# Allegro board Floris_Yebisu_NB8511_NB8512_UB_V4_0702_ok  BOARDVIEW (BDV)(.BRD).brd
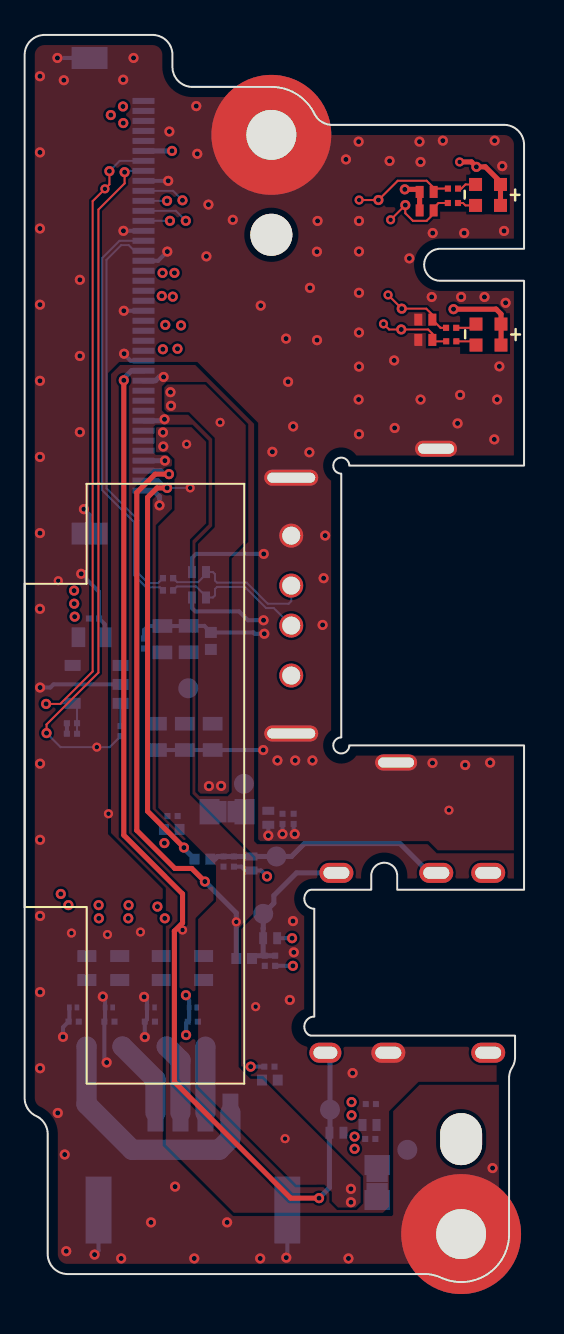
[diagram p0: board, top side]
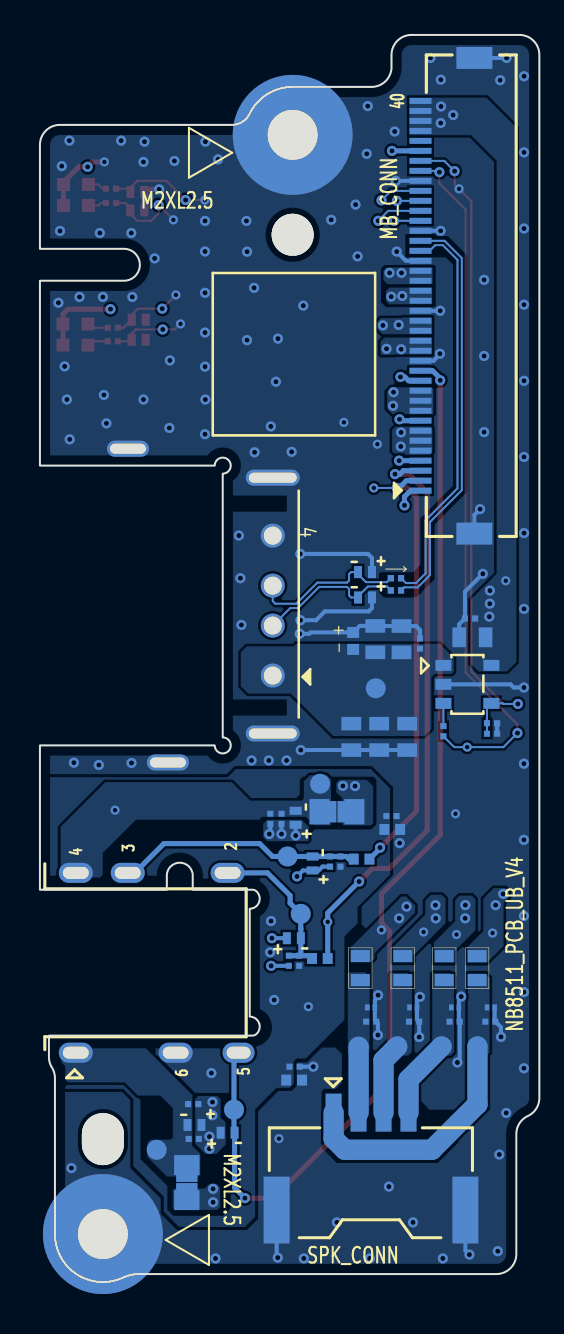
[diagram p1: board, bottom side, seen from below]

Outline 25 x 62.18 mm; copper layers: TOP, GND02, L3, L4, GND05, BOTTOM. Coordinates in mm from the lower left corner of the outline.

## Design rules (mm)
net group DP1: nets USB2_P4_TYPEA_DN_CONN USB2_P4_TYPEA_DP_CONN
net group USB2_P4_D: nets USB2_P4_DN USB2_P4_DP
nets with their own width: min track width 0.203; nets +V3P3A +V5P0A

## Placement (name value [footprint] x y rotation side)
5VUSB1  C40_1  [CMP_40]  8.19 29.49 90 bottom
CA35  C0201X5R104K6R3NTA+C0201X5R104K6R3NJA~~GRM033R60J104KE19D~~CC0201KRX5R5BB104  [C0201]  12.25 10.56 0 bottom
CA38  C0201C0G101J250NTA+C0201C0G101J250NJA~~GRM0335C1E101JD01D~~CC0201JRNPO8BN101  [C0201]  17.33 8.68 180 bottom
CA39  C0201C0G101J250NTA+C0201C0G101J250NJA~~GRM0335C1E101JD01D~~CC0201JRNPO8BN101  [C0201]  13.47 22.96 270 bottom
CA40  C0201C0G101J250NTA+C0201C0G101J250NJA~~GRM0335C1E101JD01D~~CC0201JRNPO8BN101  [C0201]  12.54 15.86 270 bottom
CA41  C0201C0G101J250NTA+C0201C0G101J250NJA~~GRM0335C1E101JD01D~~CC0201JRNPO8BN101  [C0201]  10.48 20.82 270 bottom
CA42  C0201X7R102K250NTA+C0201X7R102K250NJA~~GRM033R71E102KA01D~~CC0201KRX7R8BB102  [C0201]  2.45 12.81 0 bottom
CA43  C0201X7R102K250NTA+C0201X7R102K250NJA~~GRM033R71E102KA01D~~CC0201KRX7R8BB102  [C0201]  8.42 12.81 0 bottom
CA44  C0201X7R102K250NTA+C0201X7R102K250NJA~~GRM033R71E102KA01D~~CC0201KRX7R8BB102  [C0201]  4.24 12.81 0 bottom
CA45  C0201X7R102K250NTA+C0201X7R102K250NJA~~GRM033R71E102KA01D~~CC0201KRX7R8BB102  [C0201]  6.27 12.81 0 bottom
CA46  C0201X5R104K6R3NTA+C0201X5R104K6R3NJA~~GRM033R60J104KE19D~~CC0201KRX5R5BB104  [C0201]  7.41 23.1 0 bottom
CA47  C0201X5R222K250NTA~~CC0201KRX5R8BB222  [C0201]  17.3 6.94 180 bottom
CA48  C0201X5R222K250NTA~~CC0201KRX5R8BB222  [C0201]  12.91 22.96 270 bottom
CB37  CC0201KRX5R7BB104~~C0201X5R104M160NTA  [C0201]  5.97 31.73 90 bottom
CB38  C0603X5R106M6R3NTK~~CL10A106MQ8NNNC~~GRM188R60J106ME47D~~JMK107BJ106MA-T  [C0603_L]  3.35 32.04 0 bottom
CB39  CC0201KRX5R7BB104~~C0201X5R104M160NTA  [C0201]  3.47 32.98 0 bottom
CB400  CL10A226MQ8NRNC~~GRM188R60J226MEA0D~~JDK107BBJ226MA-T~~CC0603MRX5R5BB226  [C0603_L]  6.9 31.95 90 bottom
CB401  CL10A226MQ8NRNC~~GRM188R60J226MEA0D~~JDK107BBJ226MA-T~~CC0603MRX5R5BB226  [C0603_L]  9.41 27.06 270 bottom
CB402  CL10A226MQ8NRNC~~GRM188R60J226MEA0D~~JDK107BBJ226MA-T~~CC0603MRX5R5BB226  [C0603_L]  8.02 27.06 270 bottom
CB403  CL10A226MQ8NRNC~~GRM188R60J226MEA0D~~JDK107BBJ226MA-T~~CC0603MRX5R5BB226  [C0603_L]  6.62 27.06 270 bottom
CB405  CL10A226MQ8NRNC~~GRM188R60J226MEA0D~~JDK107BBJ226MA-T~~CC0603MRX5R5BB226  [C0603_L]  8.21 31.95 90 bottom
CB406  CC0201KRX5R7BB104~~C0201X5R104M160NTA  [C0201]  2.37 27.75 180 bottom
CHB1  EXC14CE900U  [EMI_0D85X0D65X0D5]  7.18 34.7 270 bottom
EA1  PESD5V0F1BL  [NB_ESD2_1X0D6X0D4_JX]  15.61 7.25 0 bottom
EDA1  PESD5V0F1BL  [NB_ESD2_1X0D6X0D4_JX]  17.26 7.64 180 bottom
EDA2  PESD5V0F1BL  [NB_ESD2_1X0D6X0D4_JX]  12.2 23.01 270 bottom
EDA3  PESD5V0F1BL  [NB_ESD2_1X0D6X0D4_JX]  12.29 16.99 0 bottom
EDA4  PESD5V0F1BL  [NB_ESD2_1X0D6X0D4_JX]  11.35 20.73 270 bottom
EDA5  LESD11D12CT5G  [NB_DFN0603_0D64X0D33X0D34]  2.43 13.52 180 bottom
EDA6  LESD11D12CT5G  [NB_DFN0603_0D64X0D33X0D34]  8.42 13.52 180 bottom
EDA7  LESD11D12CT5G  [NB_DFN0603_0D64X0D33X0D34]  4.22 13.52 180 bottom
EDA8  LESD11D12CT5G  [NB_DFN0603_0D64X0D33X0D34]  6.31 13.52 180 bottom
EDB2  PESD5V0F1BL  [NB_ESD2_1X0D6X0D4_JX]  8.73 35.3 180 bottom
EDB4  PESD5V0F1BL  [NB_ESD2_1X0D6X0D4_JX]  8.73 34.03 180 bottom
ESDB33  ESD9X7V-2/TR  [TVS_1X0D6X0D5_ESD5411N]  9.32 31.86 90 bottom
ESDE42  PESDTC5VB(BASIN)  [TVS2_1D01X0D61X0D4]  20.12 53.4 180 top
ESDE43  PESDTC5VB(BASIN)  [TVS2_1D01X0D61X0D4]  20.12 54.33 180 top
ESDE45  PESDTC5VB(BASIN)  [TVS2_1D01X0D61X0D4]  20.06 46.92 180 top
ESDE46  PESDTC5VB(BASIN)  [TVS2_1D01X0D61X0D4]  20.06 47.94 180 top
FBA6  PZ1608U121-2R0TF  [NB_L0603]  3.11 15.49 270 bottom
FBA7  PZ1608U121-2R0TF  [NB_L0603]  8.96 15.49 270 bottom
FBA8  PZ1608U121-2R0TF  [NB_L0603]  6.84 15.49 270 bottom
FBA9  PZ1608U121-2R0TF  [NB_L0603]  4.76 15.49 270 bottom
JDB1  FP201CH-045610M  [NB_CON40_24D1X4D5X1D5_0D5]  4.54 49.13 90 bottom
JJACK  W-18-0350-J141  [NB_PH6_14D1X10D1X4D3]  20.81 15.76 90 bottom
JSPK3  50278-00401-003  [NB_CON4_10D15X6D7X2_1D25]  8.42 4.66 180 bottom
JUSB20  WUSF11804-0A00  [NB_USB4_13D7X13D1X5D72]  14.1 33.63 270 bottom
LEDE1  A-SP1942S1B1C  [NB_LED4_1D6X1D5X0D55]  23.2 54.18 90 top
LEDE3  A-SP1942S1B1C  [NB_LED4_1D6X1D5X0D55]  23.22 47.19 90 top
NOREF  -  [unnamed]  21.85 6.93 0 top
NOREF#2  -  [#2]  12.35 57.18 270 top
NOREF#3  -  [unnamed]  12.35 52.18 0 top
RA23  0402WGJ0000TCE+0402WGJ0000TJE~~RC1005J000CS~~RC0402JR-070RL+RC0402JR-130RL~~RM04JTN0  [R0402_0D65]  8.9 20.94 0 bottom
RA24  0402WGJ0000TCE+0402WGJ0000TJE~~RC1005J000CS~~RC0402JR-070RL+RC0402JR-130RL~~RM04JTN0  [R0402_0D65]  10.99 15.97 0 bottom
RA26  WR02X4701FAL~~0201WMF4701TCE~~MCR006YRTF4701~~RC0201FR-074K7L  [R0201]  12.02 15.86 90 bottom
RA27  WR02X4701FAL~~0201WMF4701TCE~~MCR006YRTF4701~~RC0201FR-074K7L  [R0201]  9.96 20.82 90 bottom
RA28  0402WGJ0000TCE+0402WGJ0000TJE~~RC1005J000CS~~RC0402JR-070RL+RC0402JR-130RL~~RM04JTN0  [R0402_0D65]  12.28 9.89 0 bottom
RA29  0402WGJ0000TCE+0402WGJ0000TJE~~RC1005J000CS~~RC0402JR-070RL+RC0402JR-130RL~~RM04JTN0  [R0402_0D65]  7.36 22.43 0 bottom
RB1  0201WMJ0000TCE+0201WMJ0000TJE~~MCR006YRTJ000~~RC0201JR-070RL+RC0201JR-130RL~~WR02X000PAL  [R0201]  7.18 34.39 0 bottom
RB42  0201WMJ0000TCE+0201WMJ0000TJE~~MCR006YRTJ000~~RC0201JR-070RL+RC0201JR-130RL~~WR02X000PAL  [R0201]  7.18 35 0 bottom
RB43  0201WMJ0000TCE+0201WMJ0000TJE~~MCR006YRTJ000~~RC0201JR-070RL+RC0201JR-130RL~~WR02X000PAL  [R0201]  4.8 27.34 90 bottom
RB368  0201WMJ0104TCE~~MCR006YRTJ104~~RC0201JR-07100KL~~WR02X104JAL  [R0201]  2.37 27.22 0 bottom
RE388  res  [R0201]  21.44 53.77 0 top
RE389  0201WMJ0331TCE~~MCR006YRTJ331~~RC0201JR-07330RL~~WR02X331JAL  [R0201]  21.44 54.49 0 top
RE444  res  [R0201]  21.36 46.85 0 top
RE445  0201WMJ0331TCE~~MCR006YRTJ331~~RC0201JR-07330RL~~WR02X331JAL  [R0201]  21.35 47.53 0 top
SH6042  SHUNT_LOCAL  [SHUNT_0805]  17.65 4.76 90 bottom
SH6043  SHUNT_LOCAL  [SHUNT_0805]  10.13 23.31 0 bottom
TH1  -  [NB_PTHC2D5HC6]  12.35 57.18 0 top
TH3  -  [NB_PTHC2D5HC6]  21.85 2.18 0 top
TP119  40MIL  [CMP_40]  15.29 8.41 180 bottom
TP120  40MIL  [CMP_40]  12.6 21.08 90 bottom
TP121  40MIL  [CMP_40]  11.94 18.21 270 bottom
TP122  40MIL  [CMP_40]  19.16 6.4 180 bottom
TP123  40MIL  [CMP_40]  10.98 24.71 180 bottom
TP124  40MIL  [CMP_40]  4.9 11.57 180 bottom
TP126  40MIL  [CMP_40]  9.05 11.57 180 bottom
TP127  40MIL  [CMP_40]  3.1 11.57 180 bottom
TP128  40MIL  [CMP_40]  7.11 11.57 180 bottom
UB1  G517F1T11U  [NB_SOT23_5_2D95X1D6X1D4]  3.6 29.69 180 bottom

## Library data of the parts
5VUSB1 = TESTPAD_CIR: room: USB2P0
CA35 CA46 = cap: room: CODEC
CA38-CA41 = cap: room: AUDIO_JACK
CA42-CA45 = cap: room: AUDIO_SPK
CA47 CA48 = CAP: room: SOC
CB37 CB39 CB400-CB403 CB405 CB406 = cap: room: USB2P0
CB38 = CAP: room: USB2P0
CHB1 = EXC14CE900U: room: USB2P0
EA1 EDA1-EDA4 = ESD9N5BM_2TR: room: AUDIO_JACK
EDA5-EDA8 = ESD9N12BA_2_TR: room: AUDIO_SPK
EDB2 EDB4 = ESD9N5BM_2TR: room: USB2P0
ESDB33 = ESD5411N: room: USB2P0
ESDE42 ESDE43 ESDE45 ESDE46 = PESDTC5VB_5: room: LED
FBA6-FBA9 = UPZ1608U220-6R0TF: room: AUDIO_SPK
JDB1 = FPC-50PIN_1: room: DB CONN
JJACK = 2SJ2271-005111_6: room: OCD_AD
JSPK3 = SPK_1: room: FAN
JUSB20 = MINI USB_1: room: USB2P0
LEDE1 LEDE3 = LTST-C195TBKFKT_0: room: LED
RA23 RA24 RA26-RA29 = res: room: AUDIO_JACK
RB1 RB42 RB43 = res: room: USB2P0
RB368 = RES: room: USB2P0
RE388 RE389 RE444 RE445 = res: room: LED
SH6042 SH6043 = SHUNT_LOCAL_3: room: AUDIO_JACK
TH1 TH3 = THERM_HOLE: room: HOLE
TP119-TP123 = TP: room: AUDIO_JACK
TP124 TP126-TP128 = TP: room: AUDIO_SPK
UB1 = RT9742EGJ5: room: USB2P0

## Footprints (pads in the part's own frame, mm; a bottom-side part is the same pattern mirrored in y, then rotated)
C0201
  rect 0.305x0.305 smd: 1(-0.254,0) 2(0.254,0)
C0603_L
  rect 0.68x0.99 smd: 1(-0.66,0) 2(0.66,0)
CMP_40
  round 1 smd: 1(0,0)
EMI_0D85X0D65X0D5
  rect 0.305x0.305 smd: 1(-0.305,0.254) 2(0.305,0.254) 3(0.305,-0.254) 4(-0.305,-0.254)
NB_CON4_10D15X6D7X2_1D25
  rect 0.8x1.9 smd: 1(-1.875,3.6) 2(-0.625,3.6) 3(0.625,3.6) 4(1.875,3.6)
  rect 1.3x3.35 smd: 5(-4.725,-1.275) 6(4.725,-1.275)
NB_CON40_24D1X4D5X1D5_0D5
  rect 0.3x1.1 smd: 1(-9.75,1.41) 2(-9.25,1.41) 3(-8.75,1.41) 4(-8.25,1.41) 5(-7.75,1.41) 6(-7.25,1.41) 7(-6.75,1.41) 8(-6.25,1.41) 9(-5.75,1.41) 10(-5.25,1.41) 11(-4.75,1.41) 12(-4.25,1.41) 13(-3.75,1.41) 14(-3.25,1.41) 15(-2.75,1.41) 16(-2.25,1.41) 17(-1.75,1.41) 18(-1.25,1.41) 19(-0.75,1.41) 20(-0.25,1.41) 21(0.25,1.41) 22(0.75,1.41) 23(1.25,1.41) 24(1.75,1.41) 25(2.25,1.41) 26(2.75,1.41) 27(3.25,1.41) 28(3.75,1.41) 29(4.25,1.41) 30(4.75,1.41) 31(5.25,1.41) 32(5.75,1.41) 33(6.25,1.41) 34(6.75,1.41) 35(7.25,1.41) 36(7.75,1.41) 37(8.25,1.41) 38(8.75,1.41) 39(9.25,1.41) 40(9.75,1.41)
  rect 1.1x1.8 smd: 41(-11.9,-1.29) 42(11.9,-1.29)
NB_DFN0603_0D64X0D33X0D34
  rect 0.23x0.3 smd: 1(-0.19,0) 2(0.19,0)
NB_ESD2_1X0D6X0D4_JX
  rect 0.4x0.6 smd: 1(-0.35,0) 2(0.35,0)
NB_L0603
  rect 0.6x0.95 smd: 1(-0.6,0) 2(0.6,0)
NB_LED4_1D6X1D5X0D55
  rect 0.65x0.65 smd: 1(-0.525,0.625) 2(0.525,0.625) 3(0.525,-0.625) 4(-0.525,-0.625)
NB_PH6_14D1X10D1X4D3
  oval 1x1.7 hole 0.6x1.3: 1(-4.5,2.4) 2(4.5,-5.2) 3(4.5,-0.2) 4(4.5,2.4) 6(-4.5,-2.6)
  oval 1x1.6 hole 0.6x1.2: 5(-4.5,-5.75)
NB_PTHC2D5HC6
  round 6 hole 2.5: 1(0,0)
NB_SOT23_5_2D95X1D6X1D4
  rect 0.8x0.55 smd: 1(-1.2,0.95) 2(-1.2,0) 3(-1.2,-0.95) 4(1.2,-0.95) 5(1.2,0.95)
NB_USB4_13D7X13D1X5D72
  round 1.2 hole 0.9: 1(3.5,0.75) 2(1,0.75) 3(-1,0.75) 4(-3.5,0.75)
  oval 0.8x2.7 hole 0.5x2.4: 5(-6.4,0.75) 6(6.4,0.75)
  oval 0.8x2.1 hole 0.5x1.8: 7(7.85,-4.5) 8(-7.85,-6.5)
R0201
  rect 0.305x0.305 smd: 1(-0.254,0) 2(0.254,0)
R0402_0D65
  rect 0.5x0.55 smd: 1(-0.394,0) 2(0.394,0)
SHUNT_0805
  custom 0.318x0.318 smd: 1(-0.7,0) 2(0.7,0)
TVS2_1D01X0D61X0D4
  rect 0.4x0.6 smd: 1(-0.35,0) 2(0.35,0)
TVS_1X0D6X0D5_ESD5411N
  rect 0.55x0.6 smd: 1(-0.425,0) 2(0.425,0)
unnamed
  oval 2.1x2.6 hole 2.1x2.6 unplated: (0,0)

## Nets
+V3P3A: JDB1.35 LEDE1.3 LEDE1.4 LEDE3.3 LEDE3.4
+V5P0A: CB38.1 CB39.1 JDB1.37 JDB1.38 JDB1.39 JDB1.40 UB1.5(VIN)
+V5P0A_USB2: 5VUSB1.1(A) CB37.1 CB400.1 CB401.1 CB402.1 CB403.1 CB405.1 ESDB33.1(-) JUSB20.1(VBUS) UB1.1(VOUT)
GND: CA35.1 CA38.2 CA39.2 CA40.2 CA41.2 CA42.1 CA43.1 CA44.1 CA45.1 CA46.1 CA47.2 CA48.2 CB37.2 CB38.2 CB39.2 CB400.2 CB401.2 CB402.2 CB403.2 CB405.2 CB406.2 EA1.2 EDA1.2 EDA2.2 EDA3.2 EDA4.2 EDA5.2 EDA6.2 EDA7.2 EDA8.2 EDB2.2 EDB4.2 ESDB33.2(+) ESDE42.2 ESDE43.2 ESDE45.2 ESDE46.2 JDB1.14 JDB1.19 JDB1.24 JDB1.27 JDB1.32 JDB1.41(GND2) JDB1.42(GND1) JSPK3.5(G1) JSPK3.6(G2) JUSB20.4(GND4) JUSB20.5(GND13) JUSB20.6(GND12) JUSB20.7(GND11) JUSB20.8(GND10) RA28.1 RA29.1 RB368.1 TH1.1 TH3.1 UB1.2(GND)
AUD_GND: CA35.2 CA46.2 JDB1.1 JDB1.4 JDB1.8 JDB1.12 JJACK.6 RA26.1 RA27.1 RA28.2 RA29.2
EC_USB2P0_EN: CB406.1 JDB1.34 RB368.2 UB1.4(EN/EN*)
HGNDA: JDB1.9 JDB1.10 JDB1.11 SH6043.1(A[0])
HGNDA_CON: CA39.1 CA48.1 EDA2.1 JJACK.4 SH6043.2(B[0]) TP123.1
HGNDB: JDB1.5 JDB1.6 JDB1.7 SH6042.1(A[0])
HGNDB_CON: CA38.1 CA47.1 EDA1.1 JJACK.1 SH6042.2(B[0]) TP122.1
HPOL_CON: CA40.1 EDA3.1 JJACK.2 RA24.2 RA26.2 TP121.1
HPOR_CON: CA41.1 EDA4.1 JJACK.3 RA23.2 RA27.2 TP120.1
HPOUT_L_CON: JDB1.3 RA24.1
HPOUT_R_CON: JDB1.2 RA23.1
JSENSE_AB: EA1.1 JDB1.13 JJACK.5 TP119.1
LED_CHG_FULL_N: ESDE42.1 JDB1.30 RE388.1
LED_CHG_N: ESDE43.1 JDB1.31 RE389.1
LED_PWR_ON: ESDE45.1 JDB1.28 RE444.1
LED_PWR_STANDBY: ESDE46.1 JDB1.29 RE445.1
SPKL_N1: FBA7.1(FB1) JDB1.20 JDB1.21
SPKL_N1_CONN: CA43.2 EDA6.1 FBA7.2(FB2) JSPK3.2 TP126.1
SPKL_P1: FBA6.1(FB1) JDB1.22 JDB1.23
SPKL_P1_CONN: CA42.2 EDA5.1 FBA6.2(FB2) JSPK3.1 TP127.1
SPKR_N1: FBA8.1(FB1) JDB1.17 JDB1.18
SPKR_N1_CONN: CA45.2 EDA8.1 FBA8.2(FB2) JSPK3.3 TP128.1
SPKR_P1: FBA9.1(FB1) JDB1.15 JDB1.16
SPKR_P1_CONN: CA44.2 EDA7.1 FBA9.2(FB2) JSPK3.4 TP124.1
USB2_P4_DN: CHB1.2 JDB1.26 RB1.1
USB2_P4_DP: CHB1.1 JDB1.25 RB42.1
USB2_P4_TYPEA_DN_CONN: CHB1.3 EDB4.1 JUSB20.2(DM) RB1.2
USB2_P4_TYPEA_DP_CONN: CHB1.4 EDB2.1 JUSB20.3(DP) RB42.2
USB2P0_OC_N: JDB1.33 RB43.1
N33842790: RB43.2 UB1.3(FLG*)
N33850366: LEDE3.1 RE444.2
N33850368: LEDE3.2 RE445.2
N33850471: LEDE1.2 RE389.2
N33850473: LEDE1.1 RE388.2

Pads without a net: JDB1 36

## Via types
v1: diameter 0.508, hole 0.254, TOP to BOTTOM, 180 vias
v2: diameter 0.457, hole 0.229, TOP to BOTTOM, 20 vias

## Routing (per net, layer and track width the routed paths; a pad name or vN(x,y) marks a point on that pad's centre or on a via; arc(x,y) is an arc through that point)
+V3P3A: length 34.5
  TOP w0.254: LEDE1.4 LEDE1.3 23.82,54.82 23.06,55.58 v1(22.61,55.58) 22.37,55.83 v2(21.77,55.83) ; v1(21.47,48.46) 23.6,48.46 23.85,48.22 LEDE3.3 LEDE3.4
  L3 w0.254: 20.02,55.17 22.2,55.17 v1(22.61,55.58) ; 20.02,55.17 8.59,55.17 v1(7.38,56.38) ; 20.02,55.17 20.02,53.11 18.7,51.79 18.7,49.73 20.29,48.14 21.15,48.14 v1(21.47,48.46)
  BOTTOM w0.254: v1(7.38,56.38) JDB1.35
+V5P0A:
  vias: v1(2.47,34.38) v1(2.48,33.72) v1(2.5,33.07) v1(4.31,58.17) v1(4.92,58.6) v1(4.94,57.77) v2(1.68,34.87)
GND: length 59.2
  TOP w0.254: ESDE42.2 19.77,53.4 ESDE43.2 19.65,54.45 v1(19.03,54.45)
  BOTTOM w0.203: v1(13.1,1) 13.15,1.06 JSPK3.5 ; JSPK3.6 3.7,1.35 v1(3.5,1.16) ; CA39.2 13.47,22.25 v1(13.52,22.2) ; v1(4.98,46.23) 4.98,46.2 5.3,45.88 JDB1.14 ; v1(8.08,12.14) 8.08,12.73 CA43.1 8.23,12.88 EDA6.2 8.23,13.89 8.07,14.05 v1(8.07,14.13) ; JDB1.41 3.25,38.17 v1(2.97,38.45) ; CA40.2 v1(13.43,15.6) ; v1(6.02,12.04) CA45.1 6.12,12.92 EDA8.2 6.12,13.9 v1(5.98,14.05) ; CA41.2 10.85,20.57 11.05,20.38 EDA4.2 11.83,20.38 v1(12.13,20.08) ; v1(11.94,26.4) CB401.2 CB402.2 CB403.2 ; CB37.2 5.97,32.41 6.17,32.61 CB400.2 8.2,32.61 CB405.2 9,32.61 ESDB33.2 11.45,32.29 11.51,32.22 v1(12,32.22) ; CB406.2 RB368.1 ; v1(1.92,12.05) 1.92,12.53 CA42.1 2.24,12.85 EDA5.2 ; v1(3.91,14.07) 4.03,13.95 EDA7.2 4.03,12.85 CA44.1 3.99,10.89 v1(4.11,10.77) ; EDA3.2 v1(13.39,16.99) ; JDB1.27 v1(4.94,52.38) ; JDB1.19 v1(4.96,48.38) ; CA48.2 v1(12.91,22.2) ; v1(0.77,29.53) 1.29,29.53 1.44,29.69 UB1.2 ; JDB1.42 v1(1.64,61.03) ; EDA2.2 v1(12.2,22.12) ; v1(11.32,10.56) CA35.1 ; EDB4.2 8.38,33.51 8.55,33.34 10.73,33.34 11.18,32.89 v1(11.96,32.89) ; CB38.2 4.01,32.69 CB39.2 3.72,34.32 v1(2.83,35.22) ; v1(11.97,36.21) 8.58,36.21 8.38,36.01 EDB2.2 ; JDB1.24 6.68,50.88 v1(7.14,51.34) ; JDB1.32 v1(7.19,54.88)
  vias: v1(0.77,60.12) v1(0.77,56.31) v1(0.77,52.5) v1(0.77,48.69) v1(0.77,44.88) v1(0.77,41.07) v1(0.77,37.26) v1(0.77,33.46) v1(0.77,25.72) v1(0.77,21.91) v1(0.77,18.1) v1(0.77,14.29) v1(0.77,10.48) v1(1.66,8.24) v1(1.96,59.92) v1(2.01,6.16) v1(2.08,1.32) v1(2.76,49.93) v1(2.76,46.12) v1(2.76,42.31) v1(4.83,0.96) v1(4.93,59.94) v1(5.45,61.03) v1(6.33,2.77) v1(7,21.74) v1(7.24,57.35) v1(7.53,4.56) v1(8.49,0.96) v1(8.59,58.62) v1(8.64,56.23) v1(9.1,51.1) v1(9.2,53.69) v1(10.14,2.77) v1(10.42,52.93) v1(11.79,0.96) v1(11.82,48.64) v1(12.4,41.32) v1(12.66,25.88) v1(13.09,46.99) v1(13.19,44.83) v1(13.44,42.59) v1(13.54,25.88) v1(14.28,49.53) v1(14.26,41.3) v1(14.41,25.88) v1(14.66,52.88) v1(14.63,51.34) v1(14.64,46.91) v1(14.97,35) v1(14.92,32.66) v1(15.04,37.13) v1(16.08,55.95) v1(16.21,0.96) v1(16.36,8.79) v1(16.36,8.13) v1(16.52,7.06) v1(16.52,6.45) v1(16.72,56.84) v1(16.74,52.88) v1(16.74,51.35) v1(16.74,49.28) v1(16.74,47.29) v1(16.74,45.59) v1(16.72,43.94) v1(16.74,42.2) v1(18.27,55.88) v1(18.5,45.9) v1(18.52,42.52) v1(19.26,51) v1(19.77,56.84) v1(19.82,55.83) v1(19.82,43.94) v1(20.38,49.07) v1(20.43,52.27) v1(20.42,25.75) v1(20.94,56.89) v1(21.67,42.75) v1(21.8,44.17) v1(21.85,49.07) v1(22,52.27) v1(22.05,25.65) v1(23.02,49.07) v1(23.3,25.77) v1(23.42,5.48) v1(23.53,56.89) v1(23.51,41.94) v1(23.65,43.94) v1(23.76,45.6) v1(23.91,55.62) v1(24,52.37) v1(24.08,48.78) v2(4.2,23.21)
AUD_GND: length 4.6
  BOTTOM w0.254: v1(7,42.95) 6.93,42.88 JDB1.8 ; v1(7.02,40.88) JDB1.4 ; JDB1.1 6.45,39.38 6.75,39.07 v1(6.75,38.64) ; JDB1.12 6.55,44.88 6.74,45.07 v1(6.96,45.07)
  vias: v1(13.27,13.9) v1(13.43,17.84) v1(13.47,16.28) v1(16.42,10.24) v2(11.56,13.56)
EC_USB2P0_EN: length 33.3
  TOP w0.102: v1(1.07,28.71) 1.78,28.71 3.4,30.33 3.4,53.87 v2(4.02,54.48) 4.24,54.7 v1(4.24,55.37)
  BOTTOM w0.102: v1(1.07,28.71) 1.8,28.71 1.82,28.74 UB1.4 2.62,28.52 CB406.1 RB368.2 ; JDB1.34 4.76,55.88 v1(4.24,55.37)
HGNDA:
  vias: v1(7.3,44.31) v1(7.33,43.63) v1(9.23,24.6) v1(9.84,24.61) v2(9.78,42.8)
HGNDA_CON:
  vias: v2(21.24,23.39)
HGNDB:
  vias: v1(6.92,42.29) v1(6.94,41.59) v1(16.33,4.44) v1(16.33,3.77) v2(8.11,41.7) v2(13.04,6.96)
HPOL_CON: length 8.1
  BOTTOM w0.254: RA26.2 11.52,16.11 RA24.2 ; RA26.2 11.94,16.19 EDA3.1 11.94,17.48 11.94,17.48 TP121.1 12.48,18.74 12.48,19.12 13.61,20.26 JJACK.2 ; RA26.2 CA40.1
HPOR_CON: length 12.2
  BOTTOM w0.254: JJACK.3 20.26,20.26 18.79,21.72 14,21.72 13.36,21.08 TP120.1 EDA4.1 CA41.1 RA27.2 9.66,21.08 9.53,20.94 RA23.2
HPOUT_L_CON: length 29.2
  TOP w0.254: v1(9.02,19.82) 8.37,20.47 7.52,20.47 5.61,22.38 5.61,39.29 6.53,40.2 v1(7.23,40.2)
  BOTTOM w0.254: JDB1.3 6.81,40.38 6.99,40.2 v1(7.23,40.2) ; v1(9.02,19.82) 10.59,18.25 v2(10.59,17.8) RA24.1
HPOUT_R_CON: length 22.7
  TOP w0.254: v1(7.13,39.52) 6.62,39.52 6.15,39.04 6.15,23.34 v1(7.97,21.52)
  BOTTOM w0.102: v1(7.13,39.52) v2(8.29,39.52)
  BOTTOM w0.254: v1(7.97,21.52) 7.97,21.48 RA23.1 ; v1(7.13,39.52) 7.02,39.52 6.66,39.88 JDB1.2
JSENSE_AB: length 55
  TOP w0.254: v1(14.74,3.98) 13.32,3.98 7.49,9.8 7.49,17.34 7.91,17.75 7.91,19.2 4.96,22.14 v1(4.96,44.9)
  BOTTOM w0.254: v1(4.96,44.9) 4.96,45 5.35,45.38 JDB1.13 ; JJACK.5 15.29,11.03 TP119.1 15.29,7.28 EA1.1 15.26,4.5 v1(14.74,3.98)
LED_CHG_FULL_N: length 18.1
  TOP w0.102: v2(18.32,52.93) v1(19.06,53.67) 19.06,53.26 19.44,52.88 20.12,52.88 20.47,53.23 ESDE42.1 20.47,53.53 20.72,53.77 RE388.1
  L3 w0.089: v1(19.06,53.67) 18.83,53.67 17.83,54.67 7.92,54.67 v1(7.13,53.88)
  BOTTOM w0.102: JDB1.30 v1(7.13,53.88)
LED_CHG_N: length 17.6
  TOP w0.102: RE389.1 20.64,54.49 ESDE43.1 20.47,54.54 20.12,54.89 18.67,54.89 v1(17.71,53.92) v2(16.74,53.92)
  L3 w0.089: v1(17.71,53.92) 17.24,54.39 8.38,54.39 v1(7.9,53.91)
  BOTTOM w0.102: JDB1.31 7.43,54.38 v1(7.9,53.91)
LED_PWR_ON: length 18.8
  TOP w0.102: v2(17.96,47.72) 18.24,47.44 v1(18.85,47.44) 20.2,47.44 20.41,47.23 ESDE45.1 20.48,46.85 RE444.1
  L3 w0.089: v1(18.85,47.44) 18.27,48.03 13.19,48.03 8.82,52.4 7.76,52.4 v1(7.27,52.88)
  BOTTOM w0.102: JDB1.28 v1(7.27,52.88)
LED_PWR_STANDBY: length 18.9
  TOP w0.102: RE445.1 20.82,47.53 ESDE46.1 20.41,48.18 20.1,48.49 v1(18.88,48.49) v2(18.19,49.17)
  L3 w0.089: v1(18.88,48.49) 18.68,48.28 13.39,48.28 8.79,52.88 v1(8.07,52.88)
  BOTTOM w0.102: v1(8.07,52.88) 7.57,53.38 JDB1.29
SPKL_N1: length 33.6
  L4 w1.016: 8.55,49.09 9.19,49.09 10.28,48 10.28,37.58 9.77,37.08 9.77,28.07 6.09,24.39 6.09,21.32 6.65,20.77 v1(6.65,18.57)
  vias: v1(6.86,49.12) v1(7.02,17.98) v1(7.42,49.09) v2(7.91,17.4)
SPKL_N1_CONN: length 3.3
  BOTTOM w1.016: JSPK3.2 9.05,11.52
SPKL_P1: length 33.3
  L4 w1.016: v1(1.81,19.2) 1.77,19.2 1.67,19.3 1.67,26.23 4.02,28.58 4.02,49.27 4.96,50.21 5.77,50.21
  vias: v1(2.19,18.64) v1(6.9,50.28) v1(7.5,50.28) v2(2.34,17.24)
SPKL_P1_CONN: length 12.6
  BOTTOM w1.016: TP127.1 3.1,8.68 5.38,6.4 9.74,6.4 10.3,6.96 JSPK3.1
SPKR_N1: length 31.4
  L4 w1.016: v1(7.83,47.65) 8.71,46.77 8.71,38.28 7.78,37.35 7.78,28.23 4.54,24.99 4.54,20.91 5.2,20.25 v1(5.2,18.64)
  vias: v1(5.19,17.98) v1(7.04,47.67) v2(5.8,17.29)
SPKR_N1_CONN: length 3.6
  BOTTOM w1.016: JSPK3.3 7.8,10.88 TP128.1
SPKR_P1: length 30
  L4 w1.016: v1(3.7,18.64) 3.7,19.53 3.15,20.08 3.15,25.63 6.09,28.56 6.09,35.57 5.64,36.02 5.64,43.58 5.95,43.88 5.95,45.48 v1(6.92,46.45)
  vias: v1(3.71,17.98) v1(7.65,46.48) v2(4.15,17.17)
SPKR_P1_CONN: length 4
  BOTTOM w1.016: TP124.1 6.55,9.91 JSPK3.4
USB2_P4_DN: length 20.7
  BOTTOM w0.102: CHB1.2 6.77,34.54 6.09,34.54 5.48,35.15 5.48,37.81 3.88,39.4 3.88,51.02 4.75,51.88 JDB1.26
USB2_P4_DP: length 20.2
  BOTTOM w0.102: JDB1.25 5.49,51.38 5.21,51.66 4.83,51.66 4.1,50.93 4.1,39.49 5.7,37.9 5.7,35.24 6.18,34.76 6.68,34.76 CHB1.1
USB2_P4_TYPEA_DN_CONN: length 7.5
  BOTTOM w0.102: CHB1.3 7.63,34.59 8.58,34.59 9.08,34.09 EDB4.1 9.43,34.03 9.53,34.14 9.53,34.46 9.63,34.56 11.02,34.56 12.08,33.51 12.47,33.51 JUSB20.2
USB2_P4_TYPEA_DP_CONN: length 7.9
  BOTTOM w0.102: JUSB20.3 13.35,33.85 13.22,33.72 12.17,33.72 11.11,34.78 9.63,34.78 9.53,34.88 9.53,35.2 9.43,35.3 EDB2.1 9.08,35.2 8.68,34.8 7.63,34.8 CHB1.4
USB2P0_OC_N: length 34.9
  TOP w0.102: v1(1.1,27.25) 1.1,27.68 3.69,30.28 3.69,53.44 5,54.75 v1(5,55.31)
  BOTTOM w0.102: JDB1.33 5.07,55.38 v1(5,55.31) ; v1(1.1,27.25) 1.8,26.55 v2(3.61,26.55) 4.26,26.55 RB43.1
N33842790: length 1.1
  BOTTOM w0.102: UB1.3 RB43.2
N33850366: length 1.1
  TOP w0.102: RE444.2 22.41,46.85 LEDE3.1
N33850368: length 1.1
  TOP w0.102: LEDE3.2 22.41,47.53 RE445.2
N33850471: length 1
  TOP w0.102: RE389.2 21.86,54.49 22.07,54.7 LEDE1.2
N33850473: length 0.9
  TOP w0.102: LEDE1.1 22.07,53.65 21.95,53.77 RE388.2

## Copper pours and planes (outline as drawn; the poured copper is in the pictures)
+V5P0A on BOTTOM: 6.48,57.17 3.42,57.17 2.14,55.88 2.14,35.22 3.43,33.93 3.43,30.72 3.05,30.34 1.62,30.34 1.15,30.8 1.15,57.55 2.65,59.04 6.49,59.04 6.51,59.03 6.51,57.2
+V5P0A on L3: 5.32,59.1 5.55,58.88 5.55,57.56 3.36,55.37 3.36,32.92 3.1,32.66 1.73,32.66 1.18,33.22 1.17,33.22 1.17,56.28 1.17,56.28 1.17,57.94 2.34,59.1
+V5P0A_USB2 on BOTTOM: 4.98,31.71 12.17,31.71 12.3,31.59 14.65,31.59 14.95,31.29 14.95,29.59 14.58,29.23 12.45,29.23 10.32,27.1 5.76,27.1 5.41,27.45 5.41,30.04 5.24,30.21 4.39,30.21 4.28,30.32 4.28,31.02
GND on TOP: 6.4,61.67 6.75,61.53 6.89,61.18 6.89,60.58 7.33,59.52 8.4,59.07 12.35,59.07 13.35,58.79 14.6,57.4 15.4,57.17 24,57.17 24.35,57.03 24.49,56.68 24.49,51.99 20.8,51.99 19.49,50.68 20.8,49.37 24.49,49.37 24.49,41.14 16.6,41.14 15.21,41.27 15.34,39.88 15.34,27.38 15.21,25.99 16.6,26.12 24.49,26.12 24.49,21.38 20.68,21.38 20.22,21.84 11.79,21.84 11.69,21.94 11.69,42.77 8.64,45.82 4.73,45.82 4.17,45.26 4.17,22.2 6.91,19.45 6.91,6.6 10.43,3.08 18.38,3.08 18.45,3.15 18.45,8.33 19.77,9.65 23.74,9.65 23.74,2.18 22.87,0.59 21.06,0.46 20.55,0.63 20.02,0.69 2.15,0.69 1.81,0.83 1.66,1.18 1.66,7.18 1.43,7.99 0.58,8.73 0.51,8.99 0.51,61.18 0.65,61.53 1,61.67 ; 2 cut-outs
GND on BOTTOM: outline of 82 points within 0.51,0.46 24.49,61.67 ; 2 cut-outs
GND on BOTTOM: 17.07,9.09 16.11,9.09 15.96,8.94 15.96,8.02 15.7,7.77 15.7,6.65 16.16,6.19 16.72,6.19 17.23,6.7 17.23,8.94
GND on BOTTOM: 13.62,22.91 11.89,22.91 11.54,22.55 11.54,21.89 11.59,21.84 13.62,21.84 13.82,22.04 13.82,22.7
GND on GND02: 6.4,61.67 6.75,61.53 6.89,61.18 6.89,60.58 7.33,59.52 8.4,59.07 12.35,59.07 13.35,58.79 14.6,57.4 15.4,57.17 24,57.17 24.35,57.03 24.49,56.68 24.49,51.99 20.8,51.99 19.49,50.68 20.8,49.37 24.49,49.37 24.49,41.14 16.6,41.14 15.21,41.27 15.34,39.88 15.34,27.38 15.21,25.99 16.6,26.12 24.49,26.12 24.49,21.38 20.68,21.38 20.22,21.84 11.79,21.84 11.69,21.94 11.69,42.77 8.64,45.82 4.73,45.82 4.17,45.26 4.17,22.2 6.91,19.45 6.91,6.6 10.45,3.07 18.37,3.07 18.45,3.15 18.45,8.33 19.77,9.65 23.74,9.65 23.74,2.18 22.87,0.59 21.06,0.46 20.55,0.63 20.02,0.69 2.15,0.69 1.81,0.83 1.66,1.18 1.66,7.18 1.43,7.99 0.58,8.73 0.51,8.99 0.51,61.18 0.65,61.53 1,61.67
GND on L3: 6.4,61.67 6.75,61.53 6.89,61.18 6.89,60.58 7.33,59.52 8.4,59.07 12.35,59.07 13.35,58.79 14.6,57.4 15.4,57.17 24,57.17 24.35,57.03 24.49,56.68 24.49,51.99 20.8,51.99 19.49,50.68 20.8,49.37 24.49,49.37 24.49,41.14 16.6,41.14 15.21,41.27 15.34,39.88 15.34,27.38 15.21,25.99 16.6,26.12 24.49,26.12 24.49,19.97 19.16,19.97 19.16,20.11 18,21.27 16.84,20.11 16.84,19.97 14.5,19.97 13.53,19.22 13.99,18.09 13.99,13.43 13.53,12.3 14.5,11.55 24.04,11.55 24.04,11.07 23.63,10.66 23.63,9.29 23.74,9.18 23.74,2.18 22.87,0.59 21.06,0.46 20.55,0.63 20.02,0.69 2.15,0.69 1.81,0.83 1.66,1.18 1.66,7.18 1.43,7.99 0.58,8.73 0.51,8.99 0.51,61.18 0.65,61.53 1,61.67
GND on L4: 6.4,61.67 6.75,61.53 6.89,61.18 6.89,60.58 7.33,59.52 8.4,59.07 12.35,59.07 13.35,58.79 14.6,57.4 15.4,57.17 24,57.17 24.35,57.03 24.49,56.68 24.49,51.99 20.8,51.99 19.49,50.68 20.8,49.37 24.49,49.37 24.49,41.14 16.6,41.14 15.21,41.27 15.34,39.88 15.34,27.38 15.21,25.99 16.6,26.12 24.49,26.12 24.49,19.97 19.16,19.97 19.16,20.11 18,21.27 16.84,20.11 16.84,19.97 14.5,19.97 13.53,19.22 13.99,18.09 13.99,13.43 13.53,12.3 14.5,11.55 24.04,11.55 24.04,11.12 23.63,10.71 23.63,9.29 23.74,9.18 23.74,2.18 22.87,0.59 21.06,0.46 20.55,0.63 20.02,0.69 2.15,0.69 1.81,0.83 1.66,1.18 1.66,7.18 1.43,7.99 0.58,8.73 0.51,8.99 0.51,61.18 0.65,61.53 1,61.67
GND on GND05: 6.4,61.67 6.75,61.53 6.89,61.18 6.89,60.58 7.33,59.52 8.4,59.07 12.35,59.07 13.35,58.79 14.6,57.4 15.4,57.17 24,57.17 24.35,57.03 24.49,56.68 24.49,51.99 20.8,51.99 19.49,50.68 20.8,49.37 24.49,49.37 24.49,41.14 16.6,41.14 15.21,41.27 15.34,39.88 15.34,27.38 15.21,25.99 16.6,26.12 24.49,26.12 24.49,25.19 15.65,25.19 15.25,25.6 8.39,25.6 7.32,24.53 7.32,20.16 8.9,18.59 8.9,17.68 9.56,17.02 9.56,12.85 11.64,10.77 12.1,10.77 12.15,10.72 12.15,9.6 12.4,9.34 13.06,9.34 14.08,8.33 14.08,2.94 14.64,2.38 18.14,2.38 18.95,3.2 18.95,3.96 20.48,5.48 20.48,8.89 20.88,9.29 23.74,9.29 23.74,2.18 22.87,0.59 21.06,0.46 20.55,0.63 20.02,0.69 2.15,0.69 1.81,0.83 1.66,1.18 1.66,7.18 1.43,7.99 0.58,8.73 0.51,8.99 0.51,61.18 0.65,61.53 1,61.67
AUD_GND on TOP: 24.49,21.23 24.49,19.97 19.16,19.97 19.16,20.11 18,21.27 16.84,20.11 16.84,19.97 14.5,19.97 13.53,19.22 13.99,18.09 13.99,13.43 13.39,12.26 14.5,11.55 22.79,11.55 23.63,10.72 23.63,9.8 19.72,9.8 18.24,8.33 18.24,3.55 17.94,3.25 10.47,3.25 7.07,6.65 7.07,19.5 4.32,22.25 4.32,45.21 4.78,45.67 8.54,45.67 11.49,42.72 11.49,21.84 11.64,21.69 20.17,21.69 20.63,21.23 ; 2 cut-outs
AUD_GND on BOTTOM: 20.78,9.7 23.58,9.7 23.74,9.54 23.74,9.45 20.83,9.45 20.33,8.94 20.33,5.59 18.8,4.06 18.8,3.3 18.04,2.54 14.74,2.54 14.23,3.05 14.23,8.43 13.16,9.5 12.5,9.5 12.3,9.7 12.3,10.82 12.15,10.97 11.69,10.97 9.76,12.9 9.76,17.07 9.1,17.73 9.1,18.54 7.47,20.16 7.47,24.48 8.44,25.45 15.2,25.45 15.6,25.04 24.49,25.04 24.49,20.11 24.24,20.11 24.11,20.24 24.11,22.55 21.75,24.91 15.35,24.91 14.41,23.97 12.2,23.97 11.99,24.18 11.99,24.91 11.84,25.07 8.31,25.07 8.16,24.91 8.16,22.68 8.41,22.43 11.23,22.43 11.41,22.25 11.41,21.89 11.59,21.71 18.14,21.71 18.17,21.74 18.95,21.74 19.87,20.83 19.87,20.11 19.16,20.11 18,21.27 16.84,20.11 16.84,19.97 14.5,19.97 13.53,19.22 13.99,18.09 13.99,13.43 13.39,12.46 14.13,11.58 14.28,11.48 19.21,11.48 19.21,11.12 19.11,11.12 17.23,9.24 15.7,9.24 15.45,8.99 15.45,3.48 15.83,3.1 18.32,3.1 18.62,3.4 18.62,4.59 19.97,5.94 19.97,8.89
AUD_GND on GND02: 24.49,21.23 24.49,19.97 19.16,19.97 19.16,20.11 18,21.27 16.84,20.11 16.84,19.97 14.5,19.97 13.53,19.22 13.99,18.09 13.99,13.43 13.53,12.3 14.5,11.55 24.04,11.55 24.04,11.03 23.63,10.61 23.63,9.8 19.72,9.8 18.24,8.33 18.24,3.55 17.94,3.25 10.47,3.25 7.07,6.65 7.07,19.5 4.32,22.25 4.32,45.21 4.78,45.67 8.54,45.67 11.49,42.72 11.49,21.84 11.64,21.69 20.17,21.69 20.63,21.23
AUD_GND on GND05: 24.49,25.04 24.49,19.97 19.16,19.97 19.16,20.11 18,21.27 16.84,20.11 16.84,19.97 14.5,19.97 13.53,19.22 13.99,18.09 13.99,13.43 13.53,12.3 14.5,11.55 24.04,11.55 24.04,11.07 23.63,10.66 23.63,9.45 20.83,9.45 20.33,8.94 20.33,5.59 18.8,4.06 18.8,3.3 18.04,2.54 14.74,2.54 14.23,3.05 14.23,8.43 13.16,9.5 12.5,9.5 12.3,9.7 12.3,10.82 12.15,10.97 11.69,10.97 9.76,12.9 9.76,17.07 9.1,17.73 9.1,18.54 7.47,20.16 7.47,24.48 8.44,25.45 15.2,25.45 15.6,25.04
HGNDA on TOP: 8.68,36.71 9.52,37.55 9.52,42.02 8.23,43.3 7.14,43.3 7,43.45 7,44.54 7.14,44.69 9.04,44.69 11.06,42.66 11.06,36.86 10.24,36.04 10.24,24.34 10.11,24.22 9.19,24.22 9.18,24.22 8.8,24.22 8.67,24.35 8.67,24.72 8.68,24.72
HGNDA on BOTTOM: 8.32,24.59 8.32,22.75 8.43,22.63 9.82,22.63 9.85,22.66 9.85,23.97 10.17,24.29 10.17,24.76 10.01,24.91 8.64,24.91
HGNDA on BOTTOM: 7.35,43.21 5.33,43.21 5.3,43.24 5.3,44.45 5.37,44.52 5.39,44.55 7.42,44.55 7.63,44.35 7.63,43.48
HGNDA_CON on BOTTOM: 21.86,20.16 21.86,21.25 20.19,22.91 14.03,22.91 13.88,23.06 11.69,23.06 11.26,22.64 10.48,22.64 10.43,22.68 10.43,24.93 10.65,25.14 11.49,25.14 11.79,24.84 11.79,23.97 11.89,23.87 14.47,23.87 15.4,24.8 21.73,24.8 23.96,22.56 23.96,20.11 23.87,20.02 22.01,20.02
HGNDB on TOP: 13.6,4.65 8.68,9.57 8.68,17.93 9.58,18.83 9.58,20.62 6.69,23.51 6.69,37.6 7.5,38.41 7.5,40.96 7.17,41.3 6.62,41.3 6.57,41.34 6.57,42.52 6.61,42.55 8.35,42.55 9.08,41.82 9.08,37.74 8.28,36.94 8.28,24.61 8.28,24.16 11.43,21 11.43,18.21 10.71,17.49 10.71,10.54 11.3,9.95 11.89,9.95 16.82,5.02 16.82,3.77 16.56,3.51 15.69,3.51 15.38,3.82 15.38,4.28 15.01,4.66 14.64,4.66 14.63,4.65
HGNDB on BOTTOM: 18.27,4.47 18.36,4.38 18.36,3.49 18.26,3.39 16.12,3.39 15.98,3.53 15.98,4.52 16.16,4.7 16.52,4.7 16.75,4.47
HGNDB on BOTTOM: 5.46,42.58 7.2,42.58 7.37,42.42 7.37,41.35 7.27,41.25 6.76,41.25 6.69,41.17 5.5,41.17 5.36,41.31 5.36,42.48
HGNDB_CON on BOTTOM: 16.97,6.19 17.38,6.6 17.38,6.78 17.37,6.79 17.37,9.15 19.7,11.48 23.92,11.48 23.92,10.77 23.73,10.57 23.73,9.9 23.6,9.77 21.33,9.77 20.76,9.77 20.1,9.11 18.98,9.11 18.34,8.48 18.34,7.01 18.45,6.91 19.46,6.91 19.61,6.75 19.61,6.03 18.64,5.06 17.04,5.06 16.97,5.13
SPKL_N1 on BOTTOM: 6.67,19.08 6.89,19.08 9.45,16.52 9.45,15.81 9.42,15.78 8.44,15.78 8.25,15.97 8.25,16.23 6.22,18.26 6.22,18.63
SPKL_N1 on BOTTOM: 7.51,49.54 7.68,49.37 7.68,48.87 7.52,48.71 5.41,48.71 5.37,48.74 5.37,49.52 5.39,49.54
SPKL_N1 on L4: 6.71,48.56 8.54,48.56 8.63,48.65 8.63,49.49 8.59,49.53 6.81,49.53 6.5,49.21 6.5,48.78
SPKL_N1 on L4: 7.12,19.43 6.28,19.43 6.18,19.33 6.18,18.21 6.71,17.68 7.19,17.68 7.38,17.87 7.38,19.16
SPKL_N1_CONN on BOTTOM: 8.71,15.28 9.53,15.28 9.59,15.22 9.59,11.24 9.49,11.14 8.67,11.14 8.5,11.32 8.5,15.07
SPKL_P1 on BOTTOM: 2.81,17.34 3.6,16.54 3.6,15.77 3.58,15.74 2.64,15.74 1.79,16.6 1.79,18.76 1.53,19.02 1.53,19.33 1.7,19.49 2.28,19.49 2.81,18.97
SPKL_P1 on BOTTOM: 7.21,50.55 7.22,50.54 7.65,50.54 7.8,50.39 7.8,49.91 7.61,49.71 5.38,49.71 5.34,49.75 5.34,50.53 5.36,50.55
SPKL_P1 on L4: 1.87,18.32 2.38,18.32 2.65,18.59 2.65,19.1 2.09,19.66 1.4,19.66 1.23,19.48 1.23,18.97
SPKL_P1 on L4: 7.6,50.85 5.44,50.85 5.37,50.77 5.37,49.86 5.49,49.73 7.6,49.73 7.88,50.01 7.88,50.57
SPKL_P1_CONN on BOTTOM: 2.7,15.22 3.53,15.22 3.58,15.17 3.58,11.18 3.49,11.09 2.67,11.09 2.49,11.27 2.49,15.02
SPKR_N1 on BOTTOM: 4.89,19.16 5.42,19.16 5.71,18.87 5.71,18.17 7.25,16.63 7.26,16.63 7.32,16.56 7.32,15.78 7.31,15.77 6.36,15.77 6.31,15.81 6.31,16.11 4.69,17.73 4.69,18.97
SPKR_N1 on BOTTOM: 6.82,48.05 6.85,48.02 7.93,48.02 8.11,47.84 8.11,47.46 7.85,47.21 5.42,47.21 5.38,47.24 5.38,48.03 5.4,48.05
SPKR_N1 on L4: 5.72,19.43 4.76,19.43 4.68,19.35 4.68,17.68 4.81,17.55 5.64,17.55 5.72,17.62
SPKR_N1 on L4: 6.84,47.17 8.36,47.17 8.49,47.29 8.49,47.9 8.26,48.13 6.84,48.13 6.71,48 6.71,47.29
SPKR_N1_CONN on BOTTOM: 6.59,15.25 7.42,15.25 7.48,15.19 7.48,11.21 7.38,11.11 6.56,11.11 6.38,11.29 6.38,15.04
SPKR_P1 on BOTTOM: 7.27,47.04 7.27,47.04 7.75,47.04 7.96,46.83 7.96,46.23 7.91,46.17 7.27,46.17 7.25,46.2 5.42,46.2 5.39,46.24 5.39,47.02 5.41,47.04
SPKR_P1 on BOTTOM: 3.37,19.12 3.99,19.12 4.21,18.89 4.21,17.84 5.28,16.77 5.28,15.79 5.23,15.75 4.3,15.75 4.24,15.8 4.24,16.34 3.2,17.39 3.2,18.94
SPKR_P1 on L4: 4.22,19.45 3.33,19.45 3.18,19.3 3.18,17.78 3.38,17.57 3.99,17.57 4.25,17.83 4.25,19.43
SPKR_P1 on L4: 5.82,46.3 5.82,45.87 6.1,45.59 7.24,45.59 7.91,46.25 7.91,46.61 7.58,46.94 6.46,46.94
SPKR_P1_CONN on BOTTOM: 4.48,15.24 5.3,15.24 5.36,15.19 5.36,11.21 5.26,11.11 4.45,11.11 4.27,11.29 4.27,15.04

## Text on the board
Ref Des/Silkscreen Bottom: SPK_CONN | M2XL2.5 | NB8511_PCB_UB_V4 | MB_CONN
DISPLAY_BOTTOM: 140.8±0.10 | 16.1±0.10 | 9.1±0.10 | 152.1±0.10 | 159.1±0.10 | 4-∅2.3±0.10{\fNSimSun|b0|i0|c134|p49;夹具定位孔}
User.40: FIGURE | SIZE | 10.0 | 35.433 | 98.43 | 82.68 | 47.244x23.622 | 51.181x23.622 | 70.866x19.685 | 94.488x19.685 | 102.362x82.677 | DRILL CHART: TOP to BOTTOM | ALL UNITS ARE IN MILS | PLATED | NON-PLATED | QTY | 180 | 4 | 2 | 1 | 5
